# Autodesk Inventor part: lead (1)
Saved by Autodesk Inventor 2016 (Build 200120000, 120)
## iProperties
Created: 2016-09
Part Number: lead (1)
Material: Generic
Document SubType Name: Modeling
Designer: Administrator
Appearance: Generic
Author: Administrator
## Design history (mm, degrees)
feature "Body1"
feature "Body2"
feature "Body3"
feature "Body6"
feature "Body5"
feature "Body7"
body "Solid1"
body "Solid2"
body "Solid3"
body "Solid4"
body "Solid5"
body "Solid6"
